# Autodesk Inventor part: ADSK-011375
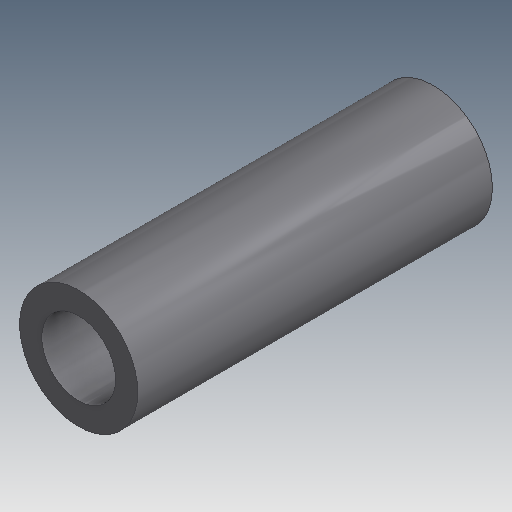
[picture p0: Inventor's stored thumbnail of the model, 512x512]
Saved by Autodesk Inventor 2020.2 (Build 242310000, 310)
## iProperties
Created: 1999-12
Part Number: ADSK-011375
Material: Acier doux
Description: TUBERD,TH,AX,03,05-13,015,MNT,VACUUM_CUP
Document SubType Name: Modeling
Designer: sspink
Density: 7.86 g/cm^3
Appearance: Metal-Steel(Polish)
Mass: 23.1169 g
Surface Area: 26.2459 cm^2
Volume: 2.94108 cm^3
Control State: 0
Checked Out: False
Master: False
Shininess: 0.0
Length Units: 11272
Angle Units: 11279
Time Units: 11290
Mass Units: 11286
Length Display Precision: 3
Angle Display Precision: 2
Compacted: True
Dimensions: 0,5x1,5x0,5 in
Mass: 0,051 lb
VLT_Material: Acier doux
Density: 0.0
Volumn: 0.0
Area: 0.0
PropertySet Name: Model Information
Author: sspink
Revision Number: -
Title: TUBERD,TH,AX,03,05-13,015,MNT,VACUUM_CUP
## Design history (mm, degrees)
node "Extrusion1" dims "d2" = 38.1, "d3" = 0
node "Solide1"
node "Corps solides"
node "Corps surfaciques"
sketch "Sketch1"
  geometry: C1 r 6.35 at (0, 0); C2 r 3.969 at (0, 0)
  constraints: 2 centre point, 1 coincident, 1 other
  dimensions: "d0" = 12.7 diameter of C1; "d1" = 7.9375 diameter of C2
